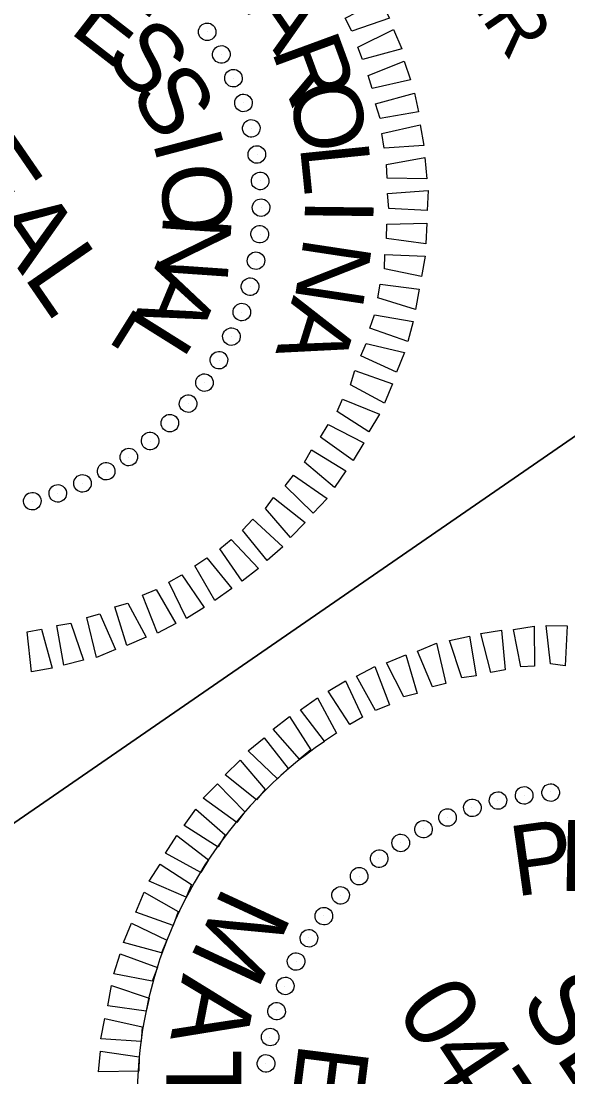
# Model space of a CAD drawing. Extents: x 2297526 to 2298642, y 599613 to 600819.
# Drawn here: x 2298526.4 to 2298556.7, y 599978.2 to 600036.6 of the extents above; entities that cross this region are included whole.
import ezdxf

# ---------------------------------------------------------------- set-up
doc = ezdxf.new("R2010")
doc.units = 0
for name, color, linetype in [('Default', 7, 'Continuous'), ('Exist DTM Drainline Cogo Elevation', 7, 'Continuous'), ('Exist DTM Drainline Cogo Point CELL', 7, 'Continuous'), ('Exist Roads EOP Cogo Elevation', 7, 'Continuous'), ('Exist Roads Soil Cogo Number', 7, 'Continuous'), ('Exist Roads Soil Cogo Point CELL', 7, 'Continuous')]:
    doc.layers.add(name, color=color, linetype=linetype)

# ---------------------------------------------------------------- blocks, each defined once
blk = doc.blocks.new('POINT_DISPLAY')
at = {"layer": 'Default'}
blk.add_line((0, 0), (0, 0), dxfattribs=at)

msp = doc.modelspace()

# ---------------------------------------------------------------- linework, layer by layer
at = {"layer": 'Exist DTM Drainline Cogo Elevation'}
for points in [[(2298537.65, 600073.144), (2298571.698, 600023.704), (2298516.106, 599985.419), (2298482.058, 600034.859)], [(2298571.698, 600023.704), (2298605.73, 599974.288), (2298550.137, 599936.003), (2298516.106, 599985.419)]]:
    msp.add_lwpolyline(points, close=True, dxfattribs=at)
at = {"layer": 'Exist DTM Drainline Cogo Point CELL'}
msp.add_arc((2298556.8, 599977.018), 23.962, 124.55406, 304.55406, dxfattribs=at)
at = {"layer": 'Exist Roads Soil Cogo Number'}
for p, q in [((2298555.748, 599993.956), (2298555.748, 599993.956)), ((2298552.825, 599993.5), (2298552.825, 599993.5)), ((2298554.282, 599993.765), (2298554.282, 599993.765)), ((2298551.39, 599993.085), (2298551.39, 599993.085)), ((2298550.05, 599992.531), (2298550.05, 599992.531)), ((2298548.721, 599991.902), (2298548.721, 599991.902)), ((2298547.44, 599991.144), (2298547.44, 599991.144)), ((2298546.236, 599990.273), (2298546.236, 599990.273)), ((2298545.156, 599989.284), (2298545.156, 599989.284)), ((2298544.086, 599988.219), (2298544.086, 599988.219)), ((2298543.148, 599987.081), (2298543.148, 599987.081)), ((2298542.343, 599985.871), (2298542.343, 599985.871)), ((2298541.642, 599984.568), (2298541.642, 599984.568)), ((2298541.026, 599983.202), (2298541.026, 599983.202)), ((2298540.531, 599981.837), (2298540.531, 599981.837)), ((2298540.188, 599980.371), (2298540.188, 599980.371)), ((2298539.948, 599978.935), (2298539.948, 599978.935))]:
    msp.add_line(p, q, dxfattribs=at)
for points in [[(2298552.428, 600000.562), (2298551.881, 600002.725), (2298553.03, 600002.902), (2298553.231, 600000.705)], [(2298554.09, 600000.886), (2298553.694, 600002.949), (2298554.843, 600003.126), (2298554.848, 600000.916)], [(2298555.745, 600001.042), (2298555.507, 600003.173), (2298556.668, 600003.153), (2298556.551, 600000.942)], [(2298549.201, 599999.773), (2298548.376, 600001.746), (2298549.427, 600002.183), (2298549.938, 599999.953)], [(2298550.823, 600000.275), (2298550.136, 600002.343), (2298551.247, 600002.575), (2298551.617, 600000.372)], [(2298547.618, 599999.216), (2298546.654, 600001.092), (2298547.733, 600001.549), (2298548.355, 599999.396)], [(2298546.047, 599998.462), (2298544.989, 600000.356), (2298546.011, 600000.895), (2298546.81, 599998.782)], [(2298544.617, 599997.682), (2298543.429, 599999.527), (2298544.384, 600000.103), (2298545.323, 599998.086)], [(2298543.209, 599996.753), (2298541.881, 599998.502), (2298542.826, 599999.153), (2298543.876, 599997.212)], [(2298541.838, 599995.768), (2298540.371, 599997.422), (2298541.278, 599998.128), (2298542.467, 599996.283)], [(2298540.618, 599994.682), (2298538.985, 599996.221), (2298539.873, 599996.955), (2298541.209, 599995.253)], [(2298539.457, 599993.513), (2298537.722, 599994.901), (2298538.553, 599995.718), (2298539.925, 599994.082)], [(2298538.352, 599992.261), (2298536.488, 599993.6), (2298537.29, 599994.398), (2298538.802, 599992.857)], [(2298537.324, 599990.897), (2298535.434, 599992.095), (2298536.085, 599992.994), (2298537.716, 599991.577)], [(2298536.362, 599989.497), (2298534.399, 599990.563), (2298535.04, 599991.537), (2298536.782, 599990.196)], [(2298535.55, 599988.118), (2298533.505, 599989.005), (2298534.118, 599989.96), (2298535.848, 599988.816)], [(2298534.825, 599986.553), (2298532.754, 599987.299), (2298533.224, 599988.401), (2298535.112, 599987.325)], [(2298534.183, 599985.046), (2298532.077, 599985.604), (2298532.52, 599986.687), (2298534.481, 599985.743)], [(2298533.673, 599983.465), (2298531.541, 599983.883), (2298531.89, 599984.983), (2298533.961, 599984.237)], [(2298533.342, 599981.803), (2298531.213, 599982.099), (2298531.42, 599983.225), (2298533.5, 599982.527)], [(2298533.058, 599980.133), (2298530.828, 599980.277), (2298531.036, 599981.403), (2298533.112, 599980.948)], [(2298532.924, 599978.483), (2298530.687, 599978.459), (2298530.801, 599979.602), (2298532.95, 599979.279)]]:
    msp.add_lwpolyline(points, close=True, dxfattribs=at)
for centre, major_axis in [((2298552.832, 599993.475), (-0.114, 0.472)), ((2298554.282, 599993.758), (-0.072, 0.481)), ((2298555.75, 599993.914), (-0.03, 0.485)), ((2298551.413, 599993.067), (-0.155, 0.461)), ((2298550.035, 599992.536), (-0.194, 0.446)), ((2298548.708, 599991.887), (-0.232, 0.427)), ((2298547.443, 599991.126), (-0.269, 0.405)), ((2298546.249, 599990.256), (-0.303, 0.38)), ((2298545.135, 599989.286), (-0.335, 0.352)), ((2298544.11, 599988.223), (-0.364, 0.322)), ((2298543.182, 599987.074), (-0.391, 0.289)), ((2298542.357, 599985.849), (-0.415, 0.254)), ((2298541.642, 599984.557), (-0.435, 0.216)), ((2298541.043, 599983.207), (-0.452, 0.178)), ((2298540.563, 599981.81), (-0.466, 0.138)), ((2298540.207, 599980.377), (-0.476, 0.096)), ((2298539.978, 599978.918), (-0.483, 0.055))]:
    msp.add_ellipse(centre, major_axis=major_axis, ratio=0.999708, dxfattribs=at)
at = {"layer": 'Exist Roads Soil Cogo Point CELL'}
for points in [[(2298544.363, 600036.796), (2298546.296, 600037.8), (2298546.816, 600036.806), (2298544.739, 600036.072)], [(2298545.061, 600035.187), (2298547.041, 600036.181), (2298547.497, 600035.103), (2298545.325, 600034.507)], [(2298545.646, 600033.623), (2298547.638, 600034.421), (2298547.981, 600033.387), (2298545.854, 600032.905)], [(2298546.035, 600032.047), (2298548.209, 600032.642), (2298548.43, 600031.605), (2298546.301, 600031.245)], [(2298546.389, 600030.404), (2298548.516, 600030.886), (2298548.72, 600029.755), (2298546.532, 600029.6)], [(2298546.657, 600028.704), (2298548.768, 600029.091), (2298548.888, 600027.904), (2298546.687, 600027.945)], [(2298546.701, 600027.094), (2298548.964, 600027.259), (2298548.906, 600026.154), (2298546.788, 600026.253)], [(2298546.679, 600025.398), (2298548.897, 600025.451), (2298548.831, 600024.298), (2298546.653, 600024.602)], [(2298546.564, 600023.721), (2298548.803, 600023.624), (2298548.595, 600022.497), (2298546.539, 600022.924)], [(2298546.308, 600022.069), (2298548.466, 600021.792), (2298548.258, 600020.667), (2298546.17, 600021.318)], [(2298545.997, 600020.379), (2298548.137, 600020.009), (2298547.836, 600018.899), (2298545.737, 600019.625)], [(2298545.533, 600018.79), (2298547.649, 600018.278), (2298547.205, 600017.195), (2298545.235, 600018.093)], [(2298544.892, 600017.281), (2298546.991, 600016.555), (2298546.548, 600015.471), (2298544.65, 600016.5)], [(2298544.213, 600015.707), (2298546.267, 600014.867), (2298545.673, 600013.886), (2298543.914, 600015.011)], [(2298543.42, 600014.301), (2298545.392, 600013.282), (2298544.799, 600012.299), (2298543, 600013.602)], [(2298542.504, 600012.891), (2298544.404, 600011.74), (2298543.772, 600010.814), (2298542.112, 600012.211)], [(2298541.495, 600011.5), (2298543.37, 600010.208), (2298542.585, 600009.382), (2298541.046, 600010.904)], [(2298540.391, 600010.248), (2298542.153, 600008.879), (2298541.341, 600008.033), (2298539.94, 600009.65)], [(2298539.248, 600009.051), (2298540.91, 600007.531), (2298540.041, 600006.768), (2298538.676, 600008.452)], [(2298538.047, 600007.936), (2298539.569, 600006.321), (2298538.663, 600005.614), (2298537.419, 600007.421)], [(2298536.695, 600006.923), (2298538.079, 600005.212), (2298537.134, 600004.561), (2298536.029, 600006.464)], [(2298535.305, 600005.966), (2298536.55, 600004.159), (2298535.567, 600003.564), (2298534.6, 600005.563)], [(2298533.894, 600005.159), (2298534.981, 600003.283), (2298533.959, 600002.744), (2298533.132, 600004.839)], [(2298532.324, 600004.405), (2298533.335, 600002.519), (2298532.255, 600002.063), (2298531.605, 600004.197)], [(2298530.759, 600003.82), (2298531.632, 600001.839), (2298530.581, 600001.4), (2298530.041, 600003.612)], [(2298529.157, 600003.289), (2298529.871, 600001.241), (2298528.78, 600000.98), (2298528.382, 600003.165)], [(2298527.541, 600002.956), (2298528.118, 600000.811), (2298526.987, 600000.607), (2298526.739, 600002.813)]]:
    msp.add_lwpolyline(points, close=True, dxfattribs=at)
for centre, major_axis in [((2298536.716, 600036.044), (0.4, 0.276)), ((2298537.5, 600034.792), (0.423, 0.24)), ((2298538.172, 600033.476), (0.442, 0.202)), ((2298538.726, 600032.107), (0.458, 0.163)), ((2298539.16, 600030.695), (0.47, 0.122)), ((2298539.468, 600029.25), (0.479, 0.081)), ((2298539.65, 600027.784), (0.485, 0.039)), ((2298539.703, 600026.308), (0.486, -0.004)), ((2298539.627, 600024.833), (0.484, -0.046)), ((2298539.422, 600023.37), (0.478, -0.088)), ((2298539.091, 600021.93), (0.469, -0.129)), ((2298538.636, 600020.525), (0.455, -0.17)), ((2298538.06, 600019.165), (0.439, -0.209)), ((2298537.368, 600017.86), (0.419, -0.246)), ((2298536.565, 600016.62), (0.396, -0.282)), ((2298535.657, 600015.455), (0.37, -0.315)), ((2298534.65, 600014.374), (0.341, -0.346)), ((2298533.553, 600013.385), (0.31, -0.375)), ((2298532.375, 600012.495), (0.276, -0.4)), ((2298531.123, 600011.711), (0.24, -0.423)), ((2298529.807, 600011.039), (0.202, -0.442)), ((2298528.438, 600010.484), (0.163, -0.458)), ((2298527.026, 600010.051), (0.122, -0.47))]:
    msp.add_ellipse(centre, major_axis=major_axis, ratio=0.999708, dxfattribs=at)

# ---------------------------------------------------------------- block references
at = {"layer": 'Exist Roads Soil Cogo Point CELL', "xscale": 41.411959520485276, "yscale": 41.41195952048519, "rotation": -55.44551104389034}
for p in [(2298536.724, 600036.044), (2298537.511, 600034.784), (2298538.168, 600033.472), (2298538.741, 600032.105), (2298539.183, 600030.688), (2298539.477, 600029.251), (2298539.668, 600027.784), (2298539.709, 600026.295), (2298539.656, 600024.825), (2298539.435, 600023.361), (2298539.119, 600021.914), (2298538.644, 600020.521), (2298538.075, 600019.145), (2298537.373, 600017.842), (2298536.587, 600016.603), (2298535.669, 600015.438), (2298533.564, 600013.374), (2298532.38, 600012.477), (2298531.118, 600011.69), (2298529.808, 600011.034), (2298528.441, 600010.46), (2298527.024, 600010.017)]:
    msp.add_blockref('POINT_DISPLAY', p, dxfattribs=at)

# ---------------------------------------------------------------- texts
at = {"layer": 'Exist DTM Drainline Cogo Elevation'}
for s, height, p in [('ROADWAY DESIGN', 3.00007, (2298540.645, 600061.073)), ('ENGINEER', 3.0001, (2298541.661, 600051.61))]:
    msp.add_text(s, height=height, rotation=304.55406, dxfattribs=at).set_placement(p)
at = {"layer": 'Exist Roads EOP Cogo Elevation'}
msp.add_text('5438 Wade Park Boulevard, Suite 200', height=1.80001, rotation=304.55406, dxfattribs=at).set_placement((2298509.809, 599981.109))
at = {"layer": 'Exist Roads Soil Cogo Number'}
for s, height, rotation, p in [('P', 3.897, 7.95295, (2298553.805, 599988.15)), ('R', 3.927, 358.59371, (2298556.196, 599988.486)), ('M', 4.162, 245.14861, (2298537.658, 599988.852)), ('A', 4.183, 258.96355, (2298535.386, 599983.939)), ('SEAL', 4.0489, 303.55406, (2298553.967, 599982.32)), ('047680', 4.0501, 303.55406, (2298547.12, 599981.896)), ('T', 4.159, 270.04057, (2298534.455, 599979.695)), ('E', 3.927, 262.83095, (2298541.821, 599980.143))]:
    msp.add_text(s, height=height, rotation=rotation, dxfattribs=at).set_placement(p)
at = {"layer": 'Exist Roads Soil Cogo Point CELL'}
for s, height, rotation, p in [('E', 3.807, 322.16556, (2298529.006, 600036.061)), ('A', 3.806, 304.57481, (2298538.703, 600037.396)), ('S', 3.807, 312.8101, (2298530.922, 600034.59)), ('R', 3.806, 290.17559, (2298540.253, 600035.024)), ('S', 3.807, 303.45489, (2298532.357, 600032.626)), ('SEAL', 4.0496, 304.55449, (2298520.351, 600031.432)), ('O', 3.806, 282.97565, (2298541.146, 600032.89)), ('I', 3.807, 284.74409, (2298533.67, 600030.001)), ('L', 3.806, 275.77536, (2298541.849, 600029.728)), ('O', 3.807, 275.38797, (2298534.066, 600028.588)), ('I', 3.806, 269.33506, (2298542.136, 600026.828)), ('N', 3.807, 266.0311, (2298534.291, 600026.004)), ('N', 3.806, 261.3734, (2298542.099, 600024.782)), ('A', 3.807, 247.31476, (2298533.981, 600023.41)), ('A', 3.806, 252.61661, (2298541.507, 600021.489)), ('L', 3.807, 237.95534, (2298532.828, 600020.978))]:
    msp.add_text(s, height=height, rotation=rotation, dxfattribs=at).set_placement(p)

doc.saveas('drawing.dxf')
